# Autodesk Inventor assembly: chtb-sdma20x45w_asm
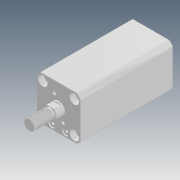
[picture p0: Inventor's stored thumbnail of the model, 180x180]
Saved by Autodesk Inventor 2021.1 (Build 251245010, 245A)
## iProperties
Company: Microsoft
Created: 2018-05
Part Number: chtb-sdma20x45w_asm
Description: STEP AP214
Document SubType Name: Assembly
Designer: user
Title: chtb-sdma20x45w_asm.STEP
Author: Windows
Revision Number: ÈÎºÎ
Sending System: SolidWorks 2015
Preprocessor: SwSTEP 2.0
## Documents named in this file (4)
- D:\Vault_2016\Projekty\Clamptek\Hydraulic\CHTB\CHTB-20\Inventor\CHTB-SDMA20x45W\chtb-sdma20x45w_asm.iam
- D:\Vault_2016\Projekty\Clamptek\Hydraulic\CHTB\CHTB-20\Inventor\CHTB-SDMA20x45W\CHTB-SDMA20X45NBT.ipt
- D:\Vault_2016\Projekty\Clamptek\Hydraulic\CHTB\CHTB-20\Inventor\CHTB-SDMA20x45W\CHTB-SDMA20X45WHSG.ipt
- D:\Vault_2016\Projekty\Clamptek\Hydraulic\CHTB\CHTB-20\Inventor\CHTB-SDMA20x45W\QG_3.ipt
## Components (3 placed, 3 different names)
1. CHTB-SDMA20X45NBT_1
2. CHTB-SDMA20X45WHSG_2
3. QG_3_3
